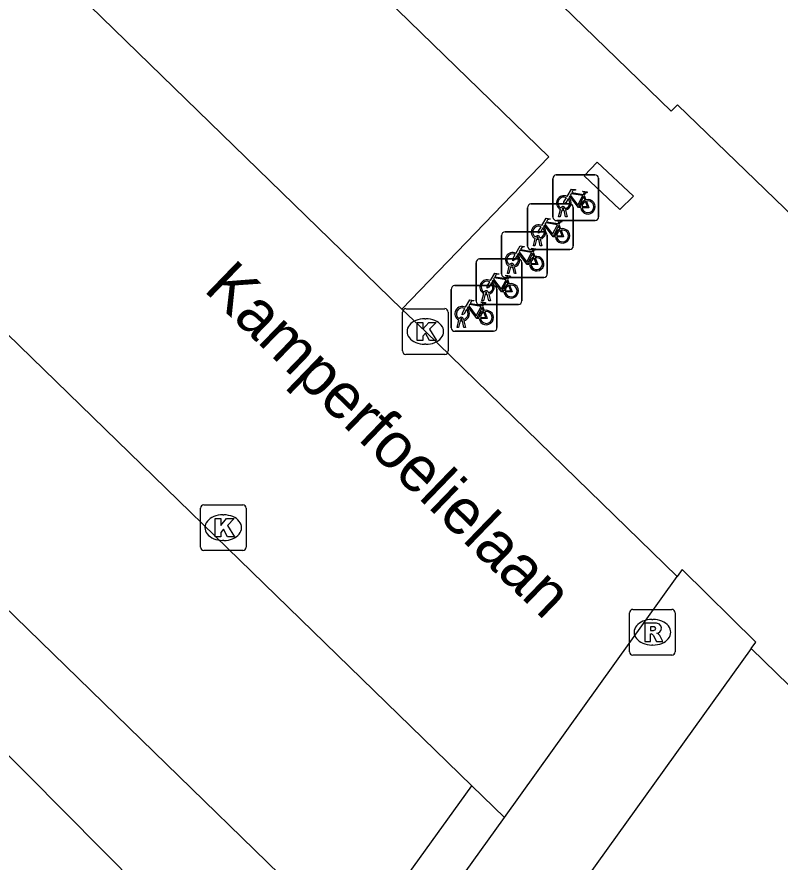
# Model space of a CAD drawing. Extents: x 162347 to 162868, y 381221 to 381813.
# Drawn here: x 162714.59 to 162731.29, y 381534.32 to 381552.81 of the extents above; entities that cross this region are included whole.
import ezdxf

# ---------------------------------------------------------------- set-up
doc = ezdxf.new("R2010")
doc.units = 0
for name, color, linetype in [('IMGEO_Fietsenrek', 7, 'Continuous'), ('IMGEO_Kolk', 7, 'Continuous'), ('IMGEO_Openbare_ruimte_label', 7, 'Continuous'), ('IMGEO_Pand', 7, 'Continuous'), ('IMGEO_Parkeervlak_open', 7, 'Continuous'), ('IMGEO_Rijbaan_lokaal_open', 7, 'Continuous'), ('IMGEO_Rioolput', 7, 'Continuous'), ('IMGEO_Voetpad_open', 7, 'Continuous')]:
    doc.layers.add(name, color=color, linetype=linetype)

msp = doc.modelspace()

# ---------------------------------------------------------------- linework, layer by layer
at = {"layer": 'IMGEO_Fietsenrek'}
for p, q in [((162726.316, 381548.433), (162726.316, 381549.274)), ((162726.316, 381549.274), (162726.316, 381548.433)), ((162726.391, 381549.358), (162727.232, 381549.358)), ((162727.232, 381549.358), (162726.391, 381549.358)), ((162727.316, 381549.283), (162727.316, 381548.442)), ((162727.316, 381548.442), (162727.316, 381549.283)), ((162727.003, 381548.907), (162727.039, 381548.812)), ((162725.762, 381547.796), (162725.762, 381548.637)), ((162725.762, 381548.637), (162725.762, 381547.796)), ((162725.837, 381548.721), (162726.678, 381548.721)), ((162726.678, 381548.721), (162725.837, 381548.721)), ((162726.762, 381548.646), (162726.762, 381547.805)), ((162726.762, 381547.805), (162726.762, 381548.646)), ((162726.443, 381548.442), (162726.482, 381548.602)), ((162726.477, 381548.442), (162726.443, 381548.442)), ((162726.512, 381548.59), (162726.477, 381548.442)), ((162726.554, 381548.614), (162726.553, 381548.618)), ((162726.595, 381548.442), (162726.561, 381548.584)), ((162726.585, 381548.625), (162726.586, 381548.618)), ((162726.593, 381548.588), (162726.628, 381548.442)), ((162726.628, 381548.442), (162726.595, 381548.442)), ((162727.241, 381548.358), (162726.4, 381548.358)), ((162726.4, 381548.358), (162727.241, 381548.358)), ((162726.449, 381548.27), (162726.485, 381548.175)), ((162725.27, 381548.114), (162726.111, 381548.114)), ((162726.111, 381548.114), (162725.27, 381548.114)), ((162725.195, 381547.189), (162725.195, 381548.03)), ((162725.195, 381548.03), (162725.195, 381547.189)), ((162725.889, 381547.805), (162725.928, 381547.965)), ((162725.958, 381547.953), (162725.923, 381547.805)), ((162726, 381547.977), (162725.999, 381547.981)), ((162726.041, 381547.805), (162726.007, 381547.947)), ((162726.031, 381547.988), (162726.032, 381547.981)), ((162726.039, 381547.951), (162726.074, 381547.805)), ((162726.195, 381548.039), (162726.195, 381547.198)), ((162726.195, 381547.198), (162726.195, 381548.039)), ((162726.687, 381547.721), (162725.846, 381547.721)), ((162725.846, 381547.721), (162726.687, 381547.721)), ((162725.923, 381547.805), (162725.889, 381547.805)), ((162726.074, 381547.805), (162726.041, 381547.805)), ((162725.882, 381547.663), (162725.918, 381547.568)), ((162724.636, 381546.593), (162724.636, 381547.434)), ((162724.636, 381547.434), (162724.636, 381546.593)), ((162724.711, 381547.518), (162725.552, 381547.518)), ((162725.552, 381547.518), (162724.711, 381547.518)), ((162725.322, 381547.198), (162725.361, 381547.358)), ((162725.391, 381547.346), (162725.356, 381547.198)), ((162725.433, 381547.37), (162725.432, 381547.374)), ((162725.474, 381547.198), (162725.44, 381547.34)), ((162725.464, 381547.381), (162725.465, 381547.374)), ((162725.472, 381547.344), (162725.507, 381547.198)), ((162725.636, 381547.443), (162725.636, 381546.602)), ((162725.636, 381546.602), (162725.636, 381547.443)), ((162725.356, 381547.198), (162725.322, 381547.198)), ((162725.507, 381547.198), (162725.474, 381547.198)), ((162726.12, 381547.114), (162725.279, 381547.114)), ((162725.279, 381547.114), (162726.12, 381547.114)), ((162725.323, 381547.067), (162725.359, 381546.972)), ((162724.092, 381546.01), (162724.092, 381546.851)), ((162724.092, 381546.851), (162724.092, 381546.01)), ((162724.167, 381546.935), (162725.008, 381546.935)), ((162725.008, 381546.935), (162724.167, 381546.935)), ((162724.874, 381546.774), (162724.873, 381546.778)), ((162724.905, 381546.785), (162724.906, 381546.778)), ((162725.092, 381546.86), (162725.092, 381546.019)), ((162725.092, 381546.019), (162725.092, 381546.86)), ((162724.763, 381546.602), (162724.802, 381546.762)), ((162724.797, 381546.602), (162724.763, 381546.602)), ((162724.832, 381546.75), (162724.797, 381546.602)), ((162724.915, 381546.602), (162724.881, 381546.744)), ((162724.913, 381546.748), (162724.948, 381546.602)), ((162724.948, 381546.602), (162724.915, 381546.602)), ((162725.561, 381546.518), (162724.72, 381546.518)), ((162724.72, 381546.518), (162725.561, 381546.518)), ((162724.779, 381546.484), (162724.815, 381546.389)), ((162724.219, 381546.019), (162724.258, 381546.179)), ((162724.288, 381546.167), (162724.253, 381546.019)), ((162724.33, 381546.191), (162724.329, 381546.195)), ((162724.371, 381546.019), (162724.337, 381546.161)), ((162724.361, 381546.202), (162724.362, 381546.195)), ((162724.369, 381546.165), (162724.404, 381546.019)), ((162725.017, 381545.935), (162724.176, 381545.935)), ((162724.176, 381545.935), (162725.017, 381545.935)), ((162724.253, 381546.019), (162724.219, 381546.019)), ((162724.404, 381546.019), (162724.371, 381546.019))]:
    msp.add_line(p, q, dxfattribs=at)
for points in [[(162726.629, 381548.884), (162726.724, 381549.048), (162726.81, 381549.034), (162726.812, 381549.025), (162726.756, 381549.014), (162726.729, 381548.969), (162726.985, 381548.928)], [(162726.985, 381548.928), (162727.01, 381548.977), (162727.004, 381548.981), (162726.981, 381548.985), (162726.969, 381548.992), (162726.968, 381548.995), (162726.97, 381549), (162727.065, 381548.985), (162727.067, 381548.975), (162727.057, 381548.962), (162727.045, 381548.956), (162727.031, 381548.962), (162727.003, 381548.907)], [(162726.65, 381548.832), (162726.598, 381548.742), (162726.558, 381548.717), (162726.559, 381548.764), (162726.614, 381548.858)], [(162726.925, 381548.64), (162726.875, 381548.64), (162726.684, 381548.891), (162726.665, 381548.859)], [(162726.972, 381548.903), (162726.715, 381548.944), (162726.698, 381548.915), (162726.865, 381548.695), (162726.972, 381548.903)], [(162727.02, 381548.805), (162726.99, 381548.882), (162726.881, 381548.664), (162726.924, 381548.664)], [(162726.954, 381548.664), (162727.074, 381548.663), (162727.03, 381548.777)], [(162727.05, 381548.784), (162727.105, 381548.639), (162726.955, 381548.639)], [(162726.075, 381548.247), (162726.17, 381548.411), (162726.256, 381548.397), (162726.258, 381548.388), (162726.202, 381548.377), (162726.175, 381548.332), (162726.431, 381548.291)], [(162726.418, 381548.266), (162726.161, 381548.307), (162726.144, 381548.278), (162726.311, 381548.058), (162726.418, 381548.266)], [(162726.431, 381548.291), (162726.456, 381548.34), (162726.45, 381548.344), (162726.427, 381548.348), (162726.415, 381548.355), (162726.414, 381548.358), (162726.416, 381548.363), (162726.511, 381548.348), (162726.513, 381548.338), (162726.503, 381548.325), (162726.491, 381548.319), (162726.477, 381548.325), (162726.449, 381548.27)], [(162726.096, 381548.195), (162726.044, 381548.105), (162726.004, 381548.08), (162726.005, 381548.127), (162726.06, 381548.221)], [(162726.371, 381548.003), (162726.321, 381548.003), (162726.13, 381548.254), (162726.111, 381548.222)], [(162726.466, 381548.168), (162726.436, 381548.245), (162726.327, 381548.027), (162726.37, 381548.027)], [(162726.4, 381548.027), (162726.52, 381548.026), (162726.476, 381548.14)], [(162726.496, 381548.147), (162726.551, 381548.002), (162726.401, 381548.002)], [(162725.508, 381547.64), (162725.603, 381547.804), (162725.689, 381547.79), (162725.691, 381547.781), (162725.635, 381547.77), (162725.608, 381547.725), (162725.864, 381547.684)], [(162725.864, 381547.684), (162725.889, 381547.733), (162725.883, 381547.737), (162725.86, 381547.741), (162725.848, 381547.748), (162725.847, 381547.751), (162725.849, 381547.756), (162725.944, 381547.741), (162725.946, 381547.731), (162725.936, 381547.718), (162725.924, 381547.712), (162725.91, 381547.718), (162725.882, 381547.663)], [(162725.529, 381547.588), (162725.477, 381547.498), (162725.437, 381547.473), (162725.438, 381547.52), (162725.493, 381547.614)], [(162725.804, 381547.396), (162725.754, 381547.396), (162725.563, 381547.647), (162725.544, 381547.615)], [(162725.851, 381547.659), (162725.594, 381547.7), (162725.577, 381547.671), (162725.744, 381547.451), (162725.851, 381547.659)], [(162725.899, 381547.561), (162725.869, 381547.638), (162725.76, 381547.42), (162725.803, 381547.42)], [(162725.833, 381547.42), (162725.953, 381547.419), (162725.909, 381547.533)], [(162725.929, 381547.54), (162725.984, 381547.395), (162725.834, 381547.395)], [(162724.949, 381547.044), (162725.044, 381547.208), (162725.13, 381547.194), (162725.132, 381547.185), (162725.076, 381547.174), (162725.049, 381547.129), (162725.305, 381547.088)], [(162725.305, 381547.088), (162725.33, 381547.137), (162725.324, 381547.141), (162725.301, 381547.145), (162725.289, 381547.152), (162725.288, 381547.155), (162725.29, 381547.16), (162725.385, 381547.145), (162725.387, 381547.135), (162725.377, 381547.122), (162725.365, 381547.116), (162725.351, 381547.122), (162725.323, 381547.067)], [(162724.97, 381546.992), (162724.918, 381546.902), (162724.878, 381546.877), (162724.879, 381546.924), (162724.934, 381547.018)], [(162725.245, 381546.8), (162725.195, 381546.8), (162725.004, 381547.051), (162724.985, 381547.019)], [(162725.292, 381547.063), (162725.035, 381547.104), (162725.018, 381547.075), (162725.185, 381546.855), (162725.292, 381547.063)], [(162725.34, 381546.965), (162725.31, 381547.042), (162725.201, 381546.824), (162725.244, 381546.824)], [(162725.274, 381546.824), (162725.394, 381546.823), (162725.35, 381546.937)], [(162725.37, 381546.944), (162725.425, 381546.799), (162725.275, 381546.799)], [(162724.405, 381546.461), (162724.5, 381546.625), (162724.586, 381546.611), (162724.588, 381546.602), (162724.532, 381546.591), (162724.505, 381546.546), (162724.761, 381546.505)], [(162724.426, 381546.409), (162724.374, 381546.319), (162724.334, 381546.294), (162724.335, 381546.341), (162724.39, 381546.435)], [(162724.701, 381546.217), (162724.651, 381546.217), (162724.46, 381546.468), (162724.441, 381546.436)], [(162724.748, 381546.48), (162724.491, 381546.521), (162724.474, 381546.492), (162724.641, 381546.272), (162724.748, 381546.48)], [(162724.796, 381546.382), (162724.766, 381546.459), (162724.657, 381546.241), (162724.7, 381546.241)], [(162724.761, 381546.505), (162724.786, 381546.554), (162724.78, 381546.558), (162724.757, 381546.562), (162724.745, 381546.569), (162724.744, 381546.572), (162724.746, 381546.577), (162724.841, 381546.562), (162724.843, 381546.552), (162724.833, 381546.539), (162724.821, 381546.533), (162724.807, 381546.539), (162724.779, 381546.484)], [(162724.73, 381546.241), (162724.85, 381546.24), (162724.806, 381546.354)], [(162724.826, 381546.361), (162724.881, 381546.216), (162724.731, 381546.216)]]:
    msp.add_lwpolyline(points, dxfattribs=at)
for centre, radius, start, end in [((162726.394, 381549.28), 0.0779, 92.4484, 184.2845), ((162726.394, 381549.28), 0.0779, 92.4484, 184.2845), ((162727.238, 381549.28), 0.0779, 2.4484, 94.2845), ((162727.238, 381549.28), 0.0779, 2.4484, 94.2845), ((162726.556, 381548.743), 0.159, 62.6766, 242.1369), ((162726.556, 381548.743), 0.129, 63.3192, 238.903), ((162726.556, 381548.743), 0.129, 283.6043, 43.4302), ((162726.556, 381548.743), 0.159, 283.5766, 46.6042), ((162727.083, 381548.659), 0.159, 187.0065, 105.7708), ((162725.84, 381548.643), 0.0779, 92.4484, 184.2845), ((162725.84, 381548.643), 0.0779, 92.4484, 184.2845), ((162726.536, 381548.614), 0.0499, 12.8025, 158.6934), ((162726.536, 381548.614), 0.0174, 12.8025, 163.4502), ((162726.684, 381548.643), 0.0779, 2.4484, 94.2845), ((162726.684, 381548.643), 0.0779, 2.4484, 94.2845), ((162727.083, 381548.659), 0.159, 113.3408, 178.3217), ((162727.083, 381548.659), 0.129, 113.923, 177.9556), ((162727.083, 381548.659), 0.129, 188.6715, 104.5883), ((162726.556, 381548.743), 0.159, 253.9967, 271.7867), ((162726.556, 381548.743), 0.129, 253.415, 269.0204), ((162726.002, 381548.106), 0.159, 62.6766, 242.1369), ((162726.394, 381548.436), 0.0779, 182.4484, 274.2845), ((162726.394, 381548.436), 0.0779, 182.4484, 274.2845), ((162727.238, 381548.436), 0.0779, 272.4484, 4.2845), ((162727.238, 381548.436), 0.0779, 272.4484, 4.2845), ((162725.273, 381548.036), 0.0779, 92.4484, 184.2845), ((162725.273, 381548.036), 0.0779, 92.4484, 184.2845), ((162726.002, 381548.106), 0.129, 63.3192, 238.903), ((162726.002, 381548.106), 0.129, 283.6043, 43.4302), ((162726.002, 381548.106), 0.159, 283.5766, 46.6042), ((162726.117, 381548.036), 0.0779, 2.4484, 94.2845), ((162726.117, 381548.036), 0.0779, 2.4484, 94.2845), ((162726.529, 381548.022), 0.159, 113.3408, 178.3217), ((162726.529, 381548.022), 0.159, 187.0065, 105.7708), ((162726.529, 381548.022), 0.129, 113.923, 177.9556), ((162726.529, 381548.022), 0.129, 188.6715, 104.5883), ((162725.982, 381547.977), 0.0499, 12.8025, 158.6934), ((162726.002, 381548.106), 0.159, 253.9967, 271.7867), ((162725.982, 381547.977), 0.0174, 12.8025, 163.4502), ((162726.002, 381548.106), 0.129, 253.415, 269.0204), ((162725.84, 381547.799), 0.0779, 182.4484, 274.2845), ((162725.84, 381547.799), 0.0779, 182.4484, 274.2845), ((162726.684, 381547.799), 0.0779, 272.4484, 4.2845), ((162726.684, 381547.799), 0.0779, 272.4484, 4.2845), ((162725.435, 381547.499), 0.159, 62.6766, 242.1369), ((162725.435, 381547.499), 0.129, 63.3192, 238.903), ((162725.435, 381547.499), 0.129, 283.6043, 43.4302), ((162725.435, 381547.499), 0.159, 283.5766, 46.6042), ((162725.558, 381547.44), 0.0779, 2.4484, 94.2845), ((162725.558, 381547.44), 0.0779, 2.4484, 94.2845), ((162725.962, 381547.415), 0.159, 113.3408, 178.3217), ((162725.962, 381547.415), 0.159, 187.0065, 105.7708), ((162725.962, 381547.415), 0.129, 113.923, 177.9556), ((162725.962, 381547.415), 0.129, 188.6715, 104.5883), ((162724.714, 381547.44), 0.0779, 92.4484, 184.2845), ((162724.714, 381547.44), 0.0779, 92.4484, 184.2845), ((162725.415, 381547.37), 0.0499, 12.8025, 158.6934), ((162725.435, 381547.499), 0.159, 253.9967, 271.7867), ((162725.415, 381547.37), 0.0174, 12.8025, 163.4502), ((162725.435, 381547.499), 0.129, 253.415, 269.0204), ((162725.273, 381547.192), 0.0779, 182.4484, 274.2845), ((162725.273, 381547.192), 0.0779, 182.4484, 274.2845), ((162726.117, 381547.192), 0.0779, 272.4484, 4.2845), ((162726.117, 381547.192), 0.0779, 272.4484, 4.2845), ((162724.876, 381546.903), 0.159, 62.6766, 242.1369), ((162724.876, 381546.903), 0.129, 63.3192, 238.903), ((162724.876, 381546.903), 0.129, 283.6043, 43.4302), ((162724.876, 381546.903), 0.159, 283.5766, 46.6042), ((162725.403, 381546.819), 0.159, 113.3408, 178.3217), ((162725.403, 381546.819), 0.159, 187.0065, 105.7708), ((162724.17, 381546.857), 0.0779, 92.4484, 184.2845), ((162724.17, 381546.857), 0.0779, 92.4484, 184.2845), ((162724.856, 381546.774), 0.0499, 12.8025, 158.6934), ((162724.856, 381546.774), 0.0174, 12.8025, 163.4502), ((162724.876, 381546.903), 0.129, 253.415, 269.0204), ((162725.014, 381546.857), 0.0779, 2.4484, 94.2845), ((162725.014, 381546.857), 0.0779, 2.4484, 94.2845), ((162725.403, 381546.819), 0.129, 113.923, 177.9556), ((162725.403, 381546.819), 0.129, 188.6715, 104.5883), ((162724.876, 381546.903), 0.159, 253.9967, 271.7867), ((162725.558, 381546.596), 0.0779, 272.4484, 4.2845), ((162725.558, 381546.596), 0.0779, 272.4484, 4.2845), ((162724.332, 381546.32), 0.159, 62.6766, 242.1369), ((162724.332, 381546.32), 0.129, 63.3192, 238.903), ((162724.332, 381546.32), 0.129, 283.6043, 43.4302), ((162724.332, 381546.32), 0.159, 283.5766, 46.6042), ((162724.714, 381546.596), 0.0779, 182.4484, 274.2845), ((162724.714, 381546.596), 0.0779, 182.4484, 274.2845), ((162724.312, 381546.191), 0.0499, 12.8025, 158.6934), ((162724.859, 381546.236), 0.159, 113.3408, 178.3217), ((162724.859, 381546.236), 0.159, 187.0065, 105.7708), ((162724.859, 381546.236), 0.129, 113.923, 177.9556), ((162724.859, 381546.236), 0.129, 188.6715, 104.5883), ((162724.332, 381546.32), 0.159, 253.9967, 271.7867), ((162724.312, 381546.191), 0.0174, 12.8025, 163.4502), ((162724.332, 381546.32), 0.129, 253.415, 269.0204), ((162724.17, 381546.013), 0.0779, 182.4484, 274.2845), ((162724.17, 381546.013), 0.0779, 182.4484, 274.2845), ((162725.014, 381546.013), 0.0779, 272.4484, 4.2845), ((162725.014, 381546.013), 0.0779, 272.4484, 4.2845)]:
    msp.add_arc(centre, radius, start, end, dxfattribs=at)
at = {"layer": 'IMGEO_Kolk'}
for p, q in [((162723.099, 381546.43), (162723.951, 381546.43)), ((162723.024, 381545.504), (162723.024, 381546.356)), ((162724.025, 381546.356), (162724.025, 381545.504)), ((162723.512, 381546.21), (162723.537, 381546.21)), ((162723.535, 381545.65), (162723.51, 381545.65)), ((162723.951, 381545.43), (162723.099, 381545.43)), ((162718.602, 381541.213), (162718.602, 381542.065)), ((162718.677, 381542.139), (162719.529, 381542.139)), ((162719.603, 381542.065), (162719.603, 381541.213)), ((162719.09, 381541.919), (162719.115, 381541.919)), ((162719.113, 381541.359), (162719.088, 381541.359)), ((162719.529, 381541.139), (162718.677, 381541.139))]:
    msp.add_line(p, q, dxfattribs=at)
for points in [[(162723.099, 381546.43), (162723.951, 381546.43)], [(162723.024, 381545.504), (162723.024, 381546.356)], [(162724.025, 381546.356), (162724.025, 381545.504)], [(162723.345, 381546.13), (162723.468, 381546.13), (162723.468, 381545.979), (162723.598, 381546.13), (162723.762, 381546.13), (162723.616, 381545.979), (162723.769, 381545.73), (162723.617, 381545.73), (162723.532, 381545.894), (162723.468, 381545.827), (162723.468, 381545.73), (162723.345, 381545.73), (162723.345, 381546.13)], [(162723.951, 381545.43), (162723.099, 381545.43)], [(162718.602, 381541.213), (162718.602, 381542.065)], [(162718.677, 381542.139), (162719.529, 381542.139)], [(162719.603, 381542.065), (162719.603, 381541.213)], [(162718.923, 381541.839), (162719.046, 381541.839), (162719.046, 381541.688), (162719.176, 381541.839), (162719.34, 381541.839), (162719.194, 381541.688), (162719.347, 381541.439), (162719.195, 381541.439), (162719.11, 381541.603), (162719.046, 381541.536), (162719.046, 381541.439), (162718.923, 381541.439), (162718.923, 381541.839)], [(162719.529, 381541.139), (162718.677, 381541.139)]]:
    msp.add_lwpolyline(points, dxfattribs=at)
for centre, start, end in [((162723.101, 381546.354), 91.552, 178.448), ((162723.101, 381546.354), 91.552, 178.448), ((162723.949, 381546.354), 1.552, 88.448), ((162723.949, 381546.354), 1.552, 88.448), ((162723.101, 381545.506), 181.552, 268.448), ((162723.101, 381545.506), 181.552, 268.448), ((162723.949, 381545.506), 271.552, 358.448), ((162723.949, 381545.506), 271.552, 358.448), ((162718.679, 381542.063), 91.552, 178.448), ((162718.679, 381542.063), 91.552, 178.448), ((162719.527, 381542.063), 1.552, 88.448), ((162719.527, 381542.063), 1.552, 88.448), ((162718.679, 381541.215), 181.552, 268.448), ((162718.679, 381541.215), 181.552, 268.448), ((162719.527, 381541.215), 271.552, 358.448), ((162719.527, 381541.215), 271.552, 358.448)]:
    msp.add_arc(centre, 0.0765, start, end, dxfattribs=at)
for centre, major_axis, ratio, start_param, end_param in [((162723.511, 381545.93), (-0.387, 0.002), 0.722429, 4.712389, 7.853982), ((162723.536, 381545.93), (-0.39, 0.002), 0.717154, 1.570796, 4.712389), ((162719.089, 381541.639), (-0.387, 0.002), 0.722429, 4.712389, 7.853982), ((162719.114, 381541.639), (-0.39, 0.002), 0.717154, 1.570796, 4.712389)]:
    msp.add_ellipse(centre, major_axis=major_axis, ratio=ratio, start_param=start_param, end_param=end_param, dxfattribs=at)
at = {"layer": 'IMGEO_Pand'}
for points in [[(162731.819, 381548.213), (162729.043, 381550.887), (162728.906, 381550.749), (162701.975, 381576.843), (162700.092, 381574.95), (162698.199, 381576.833), (162698.296, 381576.933), (162696.8, 381578.375), (162698.869, 381580.518), (162699.221, 381580.178), (162699.971, 381580.954), (162703.019, 381584.107), (162701.127, 381585.931), (162705.36, 381590.307), (162703.503, 381592.104), (162703.602, 381592.22)], [(162728.079, 381548.891), (162727.783, 381548.603), (162727.004, 381549.334), (162727.286, 381549.636), (162728.079, 381548.891)]]:
    msp.add_lwpolyline(points, dxfattribs=at)
at = {"layer": 'IMGEO_Parkeervlak_open'}
for points in [[(162723.009, 381546.422), (162726.23, 381549.751), (162702.056, 381573.223), (162698.843, 381569.907)], [(162721.991, 381532.446), (162693.056, 381560.603)], [(162691.831, 381559.425), (162720.561, 381530.446)], [(162721.991, 381532.446), (162724.543, 381535.989)]]:
    msp.add_lwpolyline(points, dxfattribs=at)
at = {"layer": 'IMGEO_Rijbaan_lokaal_open'}
for points in [[(162698.843, 381569.907), (162723.009, 381546.422)], [(162724.543, 381535.989), (162696.161, 381563.585), (162693.056, 381560.603)], [(162729.038, 381540.567), (162723.525, 381545.93), (162723.009, 381546.422)], [(162725.255, 381535.297), (162729.038, 381540.567)], [(162730.657, 381538.992), (162726.872, 381533.722)], [(162735.052, 381534.717), (162730.657, 381538.992)], [(162725.255, 381535.297), (162724.543, 381535.989)]]:
    msp.add_lwpolyline(points, dxfattribs=at)
at = {"layer": 'IMGEO_Rioolput'}
for p, q in [((162727.994, 381538.925), (162727.994, 381539.777)), ((162728.069, 381539.851), (162728.921, 381539.851)), ((162728.995, 381539.777), (162728.995, 381538.925)), ((162728.482, 381539.631), (162728.507, 381539.631)), ((162728.505, 381539.071), (162728.48, 381539.071)), ((162728.921, 381538.851), (162728.069, 381538.851))]:
    msp.add_line(p, q, dxfattribs=at)
for points in [[(162727.994, 381538.925), (162727.994, 381539.777)], [(162728.069, 381539.851), (162728.921, 381539.851)], [(162728.995, 381539.777), (162728.995, 381538.925)], [(162728.583, 381539.549), (162728.331, 381539.551), (162728.331, 381539.151)], [(162728.509, 381539.47), (162728.455, 381539.47), (162728.455, 381539.389)], [(162728.455, 381539.389), (162728.507, 381539.389)], [(162728.331, 381539.151), (162728.455, 381539.151), (162728.455, 381539.313), (162728.466, 381539.313)], [(162728.513, 381539.284), (162728.584, 381539.151), (162728.724, 381539.151), (162728.659, 381539.277)], [(162728.921, 381538.851), (162728.069, 381538.851)]]:
    msp.add_lwpolyline(points, dxfattribs=at)
for centre, radius, start, end in [((162728.071, 381539.775), 0.0765, 91.552, 178.448), ((162728.071, 381539.775), 0.0765, 91.552, 178.448), ((162728.919, 381539.775), 0.0765, 1.552, 88.448), ((162728.919, 381539.775), 0.0765, 1.552, 88.448), ((162728.491, 381539.578), 0.19, 274.7715, 282.9687), ((162728.515, 381539.374), 0.0964, 77.0061, 93.1865), ((162728.529, 381539.431), 0.0378, 276.6634, 79.6772), ((162728.582, 381539.439), 0.109, 350.3612, 89.416), ((162728.58, 381539.439), 0.112, 277.5842, 350.9817), ((162728.465, 381539.26), 0.0533, 26.0293, 88.6989), ((162728.564, 381539.224), 0.108, 29.5134, 73.7905), ((162728.071, 381538.927), 0.0765, 181.552, 268.448), ((162728.071, 381538.927), 0.0765, 181.552, 268.448), ((162728.919, 381538.927), 0.0765, 271.552, 358.448), ((162728.919, 381538.927), 0.0765, 271.552, 358.448)]:
    msp.add_arc(centre, radius, start, end, dxfattribs=at)
for centre, major_axis, ratio, start_param, end_param in [((162728.481, 381539.351), (-0.387, 0.002), 0.722429, 4.712389, 7.853982), ((162728.506, 381539.351), (-0.39, 0.002), 0.717154, 1.570796, 4.712389)]:
    msp.add_ellipse(centre, major_axis=major_axis, ratio=ratio, start_param=start_param, end_param=end_param, dxfattribs=at)
at = {"layer": 'IMGEO_Voetpad_open'}
for points in [[(162730.657, 381538.992), (162730.76, 381539.135), (162729.149, 381540.721), (162729.038, 381540.567)], [(162722.707, 381531.749), (162725.255, 381535.297)]]:
    msp.add_lwpolyline(points, dxfattribs=at)

# ---------------------------------------------------------------- texts
at = {"layer": 'IMGEO_Openbare_ruimte_label'}
msp.add_text('Kamperfoelielaan', height=1, rotation=315.9724, dxfattribs=at).set_placement((162718.653, 381546.833))

doc.saveas('drawing.dxf')
